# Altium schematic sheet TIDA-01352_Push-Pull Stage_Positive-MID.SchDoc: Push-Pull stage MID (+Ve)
size 431 x 279 mm; Date: Not shown in title block; ApprovedBy: Not shown in title block; CheckedBy: Not shown in title block; Author: Not shown in title block; CompanyName: Not shown in title block; DrawnBy: Sanjay Pithadia; Engineer: Sanjay Pithadia; Organization: Not shown in title block; Address1: Not shown in title block; Address2: Not shown in title block; Address3: Not shown in title block; Address4: Not shown in title block; DocumentNumber: 1; Revision: Use project parameter SCH_Rev; SheetNumber: 7; SheetTotal: 9; PageSetup: Record=PageOptions¦CenterHorizontal=True¦CenterVertical=True¦PrintScale=1.00¦XCorrection=1.00¦YCorrection=1.00¦PrintKind=0¦BorderSize=5000000¦LeftOffset=0¦BottomOffset=0¦Orientation=2¦PaperLength=1000¦PaperWidth=1000¦Scale=100¦PaperSource=15¦PrintQuality=600¦MediaType=1¦DitherType=10¦PaperKind=Letter¦PrintScaleMode=1
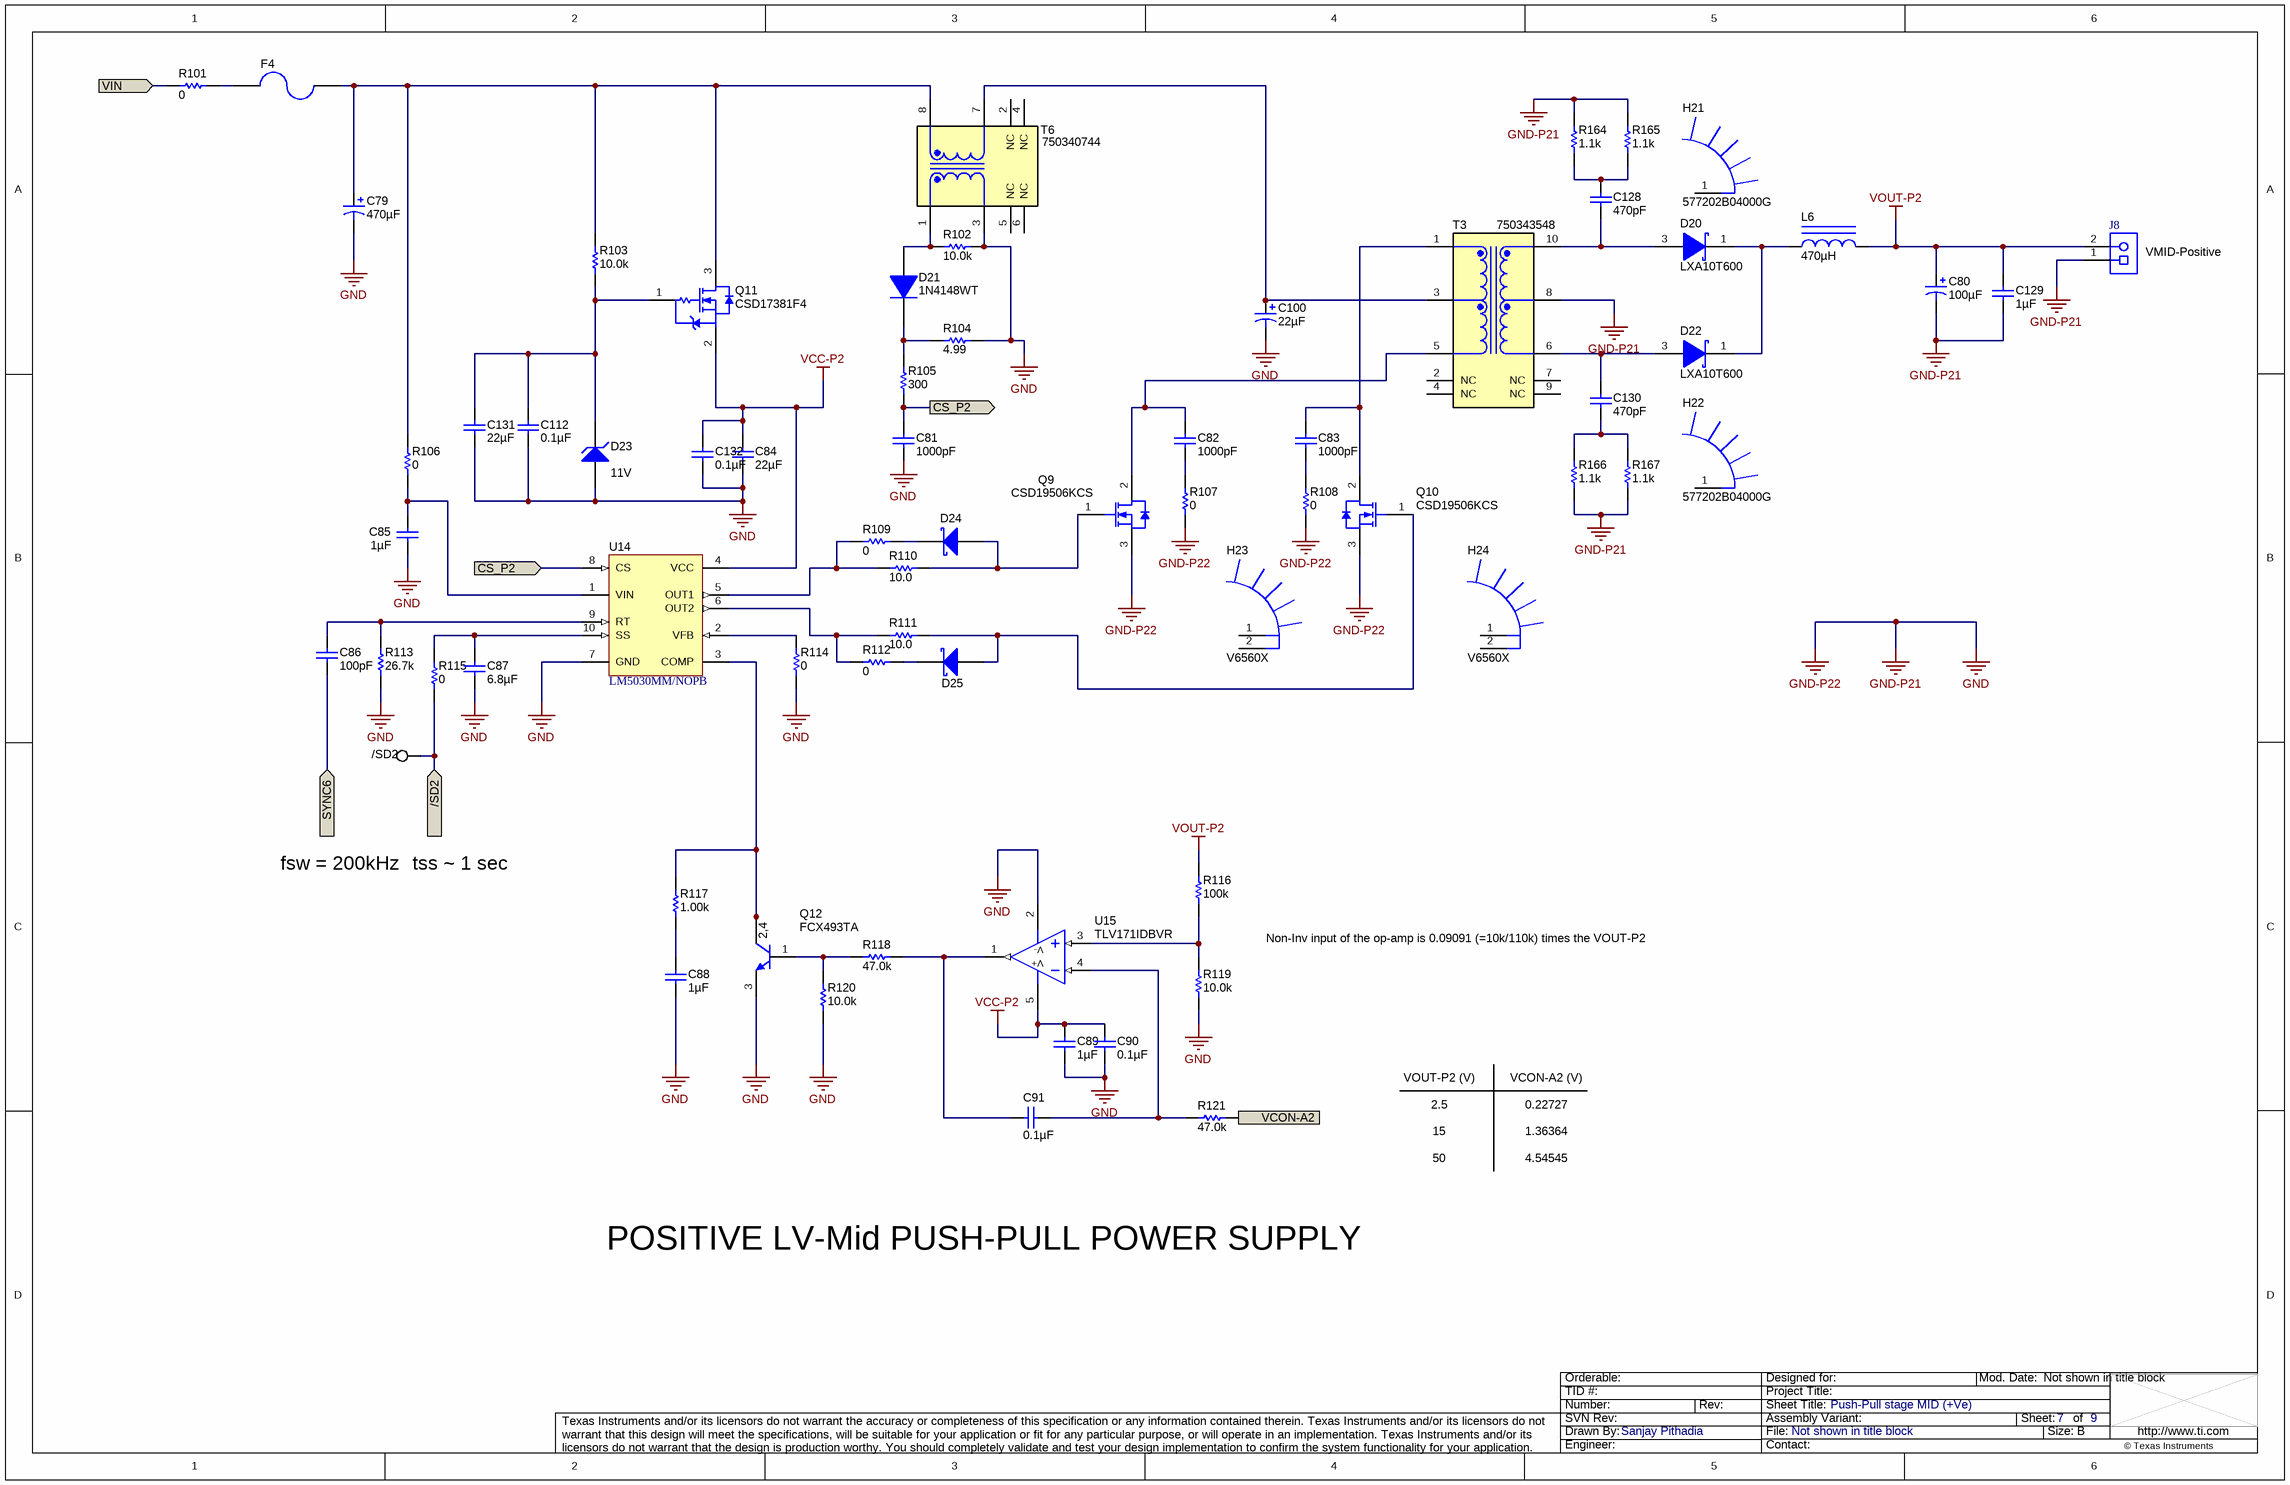
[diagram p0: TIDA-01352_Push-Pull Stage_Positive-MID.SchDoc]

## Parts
/SD2  5002  [Keystone5002]  (value not drawn)
C79  ValueDisplayed: 470µF  [WCAP-ATLI_1300x3000]  (hidden comment: 860080778023)
C80  ValueDisplayed: 100µF  [Nichicon_2000x3000_Snap]  (hidden comment: LLS2G101MELY)
C81  ValueDisplayed: 1000pF  [0603]  (hidden comment: GRM188R71E102KA01D)
C82  ValueDisplayed: 1000pF  [0603]  (hidden comment: GRM188R71E102KA01D)
C83  ValueDisplayed: 1000pF  [0603]  (hidden comment: GRM188R71E102KA01D)
C84  ValueDisplayed: 22µF  [1210_280]  (hidden comment: 12103D226MAT2A)
C85  ValueDisplayed: 1µF  [0805_HV]  (hidden comment: 08055C105KAT2A)
C86  ValueDisplayed: 100pF  [0603]  (hidden comment: 06035A101FAT2A)
C87  ValueDisplayed: 6.8µF  [0603]  (hidden comment: C1608X5R1E685K080AC)
C88  ValueDisplayed: 1µF  [0603]  (hidden comment: GMK107BJ105KA-T)
C89  ValueDisplayed: 1µF  [0805_HV]  (hidden comment: 08055C105KAT2A)
C90  ValueDisplayed: 0.1µF  [0603]  (hidden comment: 06035C104KAT2A)
C91  ValueDisplayed: 0.1µF  [0603]  (hidden comment: 06035C104KAT2A)
C100  ValueDisplayed: 22µF  [SM_RADIAL_E]  (hidden comment: EEE-FC1H220P)
C112  ValueDisplayed: 0.1µF  [0603]  (hidden comment: 06035C104KAT2A)
C128  ValueDisplayed: 470pF  [1206]  (hidden comment: VJ1206Y471KBEAT4X)
C129  ValueDisplayed: 1µF  [2220_200]  (hidden comment: GRM55DR72E105KW01L)
C130  ValueDisplayed: 470pF  [1206]  (hidden comment: VJ1206Y471KBEAT4X)
C131  ValueDisplayed: 22µF  [1210_280]  (hidden comment: 12103D226MAT2A)
C132  ValueDisplayed: 0.1µF  [0603]  (hidden comment: 06035C104KAT2A)
D20  LXA10T600  [TO-220AC]
D21  1N4148WT  [Fairchild_SOD-523F]
D22  LXA10T600  [TO-220AC]
D23  value 11V  [SMA]  (hidden comment: 1SMA5926BT3G)
D24  PMEG1030EJ,115  [SOD-323F]  (value not drawn)
D25  PMEG1030EJ,115  [SOD-323F]  (value not drawn)
F4  0679L9100-01  [Fuse_SSQ]  (value not drawn)
H21  577202B04000G  [Aavid_577202B04000G]
H22  577202B04000G  [Aavid_577202B04000G]
H23  V6560X  [ASMN_V6560X]
H24  V6560X  [ASMN_V6560X]
J8  1727010  [PhoenixConact_1727010]  (value not drawn)
L6  ValueDisplayed: 470µH  [1447440C]  (hidden comment: 1447440C)
Q9  CSD19506KCS  [KCS0003B]
Q10  CSD19506KCS  [KCS0003B]
Q11  CSD17381F4  [YJC0003A]
Q12  FCX493TA  [SOT-89-3]
R101  ValueDisplayed: 0  [5108]  (hidden comment: 5108)
R102  ValueDisplayed: 10.0k  [0603]  (hidden comment: CRCW060310K0FKEA)
R103  ValueDisplayed: 10.0k  [0603]  (hidden comment: CRCW060310K0FKEA)
R104  ValueDisplayed: 4.99  [0805_HV]  (hidden comment: CRCW08054R99FKEA)
R105  ValueDisplayed: 300  [0603]  (hidden comment: RC0603FR-07300RL)
R106  ValueDisplayed: 0  [0603]  (hidden comment: CRCW06030000Z0EA)
R107  ValueDisplayed: 0  [0603]  (hidden comment: CRCW06030000Z0EA)
R108  ValueDisplayed: 0  [0603]  (hidden comment: CRCW06030000Z0EA)
R109  ValueDisplayed: 0  [0603]  (hidden comment: CRCW06030000Z0EA)
R110  ValueDisplayed: 10.0  [0603]  (hidden comment: CRCW060310R0FKEA)
R111  ValueDisplayed: 10.0  [0603]  (hidden comment: CRCW060310R0FKEA)
R112  ValueDisplayed: 0  [0603]  (hidden comment: CRCW06030000Z0EA)
R113  ValueDisplayed: 26.7k  [0603]  (hidden comment: CRCW060326K7FKEA)
R114  ValueDisplayed: 0  [0603]  (hidden comment: CRCW06030000Z0EA)
R115  ValueDisplayed: 0  [0603]  (hidden comment: CRCW06030000Z0EA)
R116  ValueDisplayed: 100k  [1206]  (hidden comment: CRCW1206100KFKEA)
R117  ValueDisplayed: 1.00k  [0603]  (hidden comment: CRCW06031K00FKEA)
R118  ValueDisplayed: 47.0k  [0603]  (hidden comment: RC0603FR-0747KL)
R119  ValueDisplayed: 10.0k  [1206]  (hidden comment: CRCW120610K0FKEA)
R120  ValueDisplayed: 10.0k  [0603]  (hidden comment: CRCW060310K0FKEA)
R121  ValueDisplayed: 47.0k  [0603]  (hidden comment: RC0603FR-0747KL)
R164  ValueDisplayed: 1.1k  [PR01]  (hidden comment: PR01000101101JR500)
R165  ValueDisplayed: 1.1k  [PR01]  (hidden comment: PR01000101101JR500)
R166  ValueDisplayed: 1.1k  [PR01]  (hidden comment: PR01000101101JR500)
R167  ValueDisplayed: 1.1k  [PR01]  (hidden comment: PR01000101101JR500)
T3  750343548  [Wurth_750343473]
T6  750340744  [Wurth_750340744]
U14  LM5030MM/NOPB  [MUB10A_N]
U15  TLV171IDBVR  [DBV0005A_N]

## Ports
/SD2 (in), CS_P2 (in), CS_P2 (out), SYNC6 (in), VCON-A2 (in), VIN (in)

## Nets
GND: C79.2(-) C80.2(-) C81.2 C84.2 C85.2 C87.2 C88.2 C89.2 C90.2 C100.2(-) C112.2 C129.2 C131.2 C132.2 D23.2(A) J8.1 Q9.3(S) Q10.3(S) Q12.3(E) R102.1 R104.2 R107.2 R108.2 R113.1 R114.1 R119.1 R120.1 R164.2 R165.2 R166.1 R167.1 T3.8 T6.3 U14.7(GND) U15.2(V-)  [also labelled GND-P21, GND-P22]
VCC-P2: C84.1 C89.1 C90.1 C132.1 Q11.2(S) U14.4(VCC) U15.5(V+)
VOUT-P2: C80.1(+) C129.1 J8.2 L6.2 R116.2
/SD2: /SD2.1 R115.1 ; port /SD2
CS_P2: C81.1 R105.1 U14.8(CS) ; port CS_P2
SYNC6: C86.2 ; port SYNC6
VCON-A2: R121.2 ; port VCON-A2
VIN: R101.1 ; port VIN
NetC79_1: C79.1(+) F4.1 Q11.3(D) R103.2 R106.2 T6.8
NetC82_1: C82.1 Q9.2(D) T3.5
NetC82_2: C82.2 R107.1
NetC83_1: C83.1 Q10.2(D) T3.1
NetC83_2: C83.2 R108.1
NetC85_1: C85.1 R106.1 U14.1(VIN)
NetC86_1: C86.1 R113.2 U14.9(RT)
NetC87_1: C87.1 R115.2 U14.10(SS)
NetC88_1: C88.1 R117.1
NetC91_1: C91.1 R121.1 U15.4(IN-)
NetC91_2: C91.2 R118.2 U15.1(OUT)
NetC100_1: C100.1(+) T3.3 T6.7
NetC112_1: C112.1 C131.1 D23.1(K) Q11.1(G) R103.1
NetC128_1: C128.1 R164.1 R165.1
NetC128_2: C128.2 D20.3(K) T3.10
NetC130_1: C130.1 D22.3(K) T3.6
NetC130_2: C130.2 R166.2 R167.2
NetD20_1: D20.1(A) D22.1(A) L6.1
NetD21_1: D21.1(K) R104.1 R105.2
NetD21_2: D21.2(A) R102.2 T6.1
NetD24_1: D24.1(K) R109.1
NetD24_2: D24.2(A) Q9.1(G) R110.2
NetD25_1: D25.1(K) R112.1
NetD25_2: D25.2(A) Q10.1(G) R111.2
NetF4_2: F4.2 R101.2
NetQ12_1: Q12.1(B) R118.1 R120.2
NetQ12_2: Q12.2(C) Q12.4(C) R117.2 U14.3(COMP)
NetR109_2: R109.2 R110.1 U14.5(OUT1)
NetR111_1: R111.1 R112.2 U14.6(OUT2)
NetR114_2: R114.2 U14.2(VFB)
NetR116_1: R116.1 R119.2 U15.3(IN+)

Not connected (* = marked no-connect by the designer): H21 1; H22 1; H23 1 2; H24 1 2; T3 2(NC) 4(NC) 7(NC) 9(NC); T6 2(NC) 4(NC) 5(NC) 6(NC)

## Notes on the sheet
- (near J8) VMID-Positive
- fsw = 200kHz
- tss ~ 1 sec
- Non-Inv input of the op-amp is 0.09091 (=10k/110k) times the VOUT-P2
- VOUT-P2 (V)
- 2.5
- VCON-A2 (V)
- 0.22727
- 15
- 50
- 1.36364
- 4.54545
- POSITIVE LV-Mid PUSH-PULL POWER SUPPLY

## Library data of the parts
/SD2 = 5002: Test Point, Miniature, White, TH; Manufacturer: Keystone; CompType: Test Point Loop; ContactFinish: Silver
C79 = 860080778023: CAP, AL, 470 µF, 63 V, +/- 20%, TH; Manufacturer: Wurth Elektronik; Polarized: Y; CompType: Capacitor; Value: 470uF; U/M: EA; Cap_F: 0.00047; Tolerance_%: 20; Value1: Unknown; VDC_V: 63; Value2: 63V; IRMS_A: 2.225; TaMin_C: -55; TaMax_C: 105; Cap_Case: 13x30mm; SizeAreaWB_mm2: 225; SizeArea_mm2: 169; SizeX_mm: 13; SizeZ_mm: 31.5; AEC Category: Q200; AEC Qualified: N
C80 = LLS2G101MELY: CAP, AL, 100 µF, 400 V, +/- 20%, TH; Manufacturer: Nichicon; Polarized: Y; CompType: Capacitor; Value: 100uF; U/M: EA; Cap_F: 0.0001; Tolerance_%: 20; Value1: Unknown; VDC_V: 400; Value2: 400V; IRMS_A: 0.95; TaMin_C: -25; TaMax_C: 85; Cap_Case: 20x30mm; SizeAreaWB_mm2: 484; SizeZ_mm: 32; AEC Category: Q200; AEC Qualified: N
C81-C83 = GRM188R71E102KA01D: CAP, CERM, 1000 pF, 25 V, +/- 10%, X7R, 0603; Manufacturer: MuRata; Polarized: N; CompType: Capacitor; Value: 1000pF; U/M: EA; Cap_F: 0.000000001; Tolerance_%: 10; Value1: Unknown; VDC_V: 25; Value2: 25V; TaMin_C: -55; TaMax_C: 125; SizeArea_mm2: 1.28; SizeAreaWB_mm2: 4.68; SizeX_mm: 1.6; SizeY_mm: 0.8; SizeZ_mm: 1; AEC Category: Q200
C84 C131 = 12103D226MAT2A: CAP, CERM, 22 µF, 25 V, +/- 20%, X5R, 1210; Manufacturer: AVX; Polarized: N; CompType: Capacitor; Value: 22uF; U/M: EA; Cap_F: 0.000022; Tolerance_%: 20; Value1: Unknown; VDC_V: 25; Value2: 25V; TaMin_C: -55; TaMax_C: 85; Cap_Case: 1210; SizeArea_mm2: 8; SizeAreaWB_mm2: 14.7; SizeX_mm: 3.2; SizeY_mm: 2.5; SizeZ_mm: 2.8; AEC Category: Q200
C85 C89 = 08055C105KAT2A: CAP, CERM, 1 µF, 50 V, +/- 10%, X7R, 0805; Manufacturer: AVX; Polarized: N; CompType: Capacitor; Value: 1uF; U/M: EA; Cap_F: 0.000001; Tolerance_%: 10; Value1: Unknown; VDC_V: 50; Value2: 50V; TaMin_C: -55; TaMax_C: 125; Cap_Case: 0805; SizeArea_mm2: 2.5; SizeAreaWB_mm2: 6.75; SizeX_mm: 2; SizeY_mm: 1.25; SizeZ_mm: 1.45; AEC Category: Q200
C86 = 06035A101FAT2A: CAP, CERM, 100 pF, 50 V, +/- 1%, C0G/NP0, 0603; Manufacturer: AVX; Polarized: N; CompType: Capacitor; Value: 100pF; U/M: EA; Cap_F: 0.0000000001; Tolerance_%: 1; Value1: Unknown; VDC_V: 50; Value2: 50V; TaMin_C: -55; TaMax_C: 125; SizeArea_mm2: 1.28; SizeAreaWB_mm2: 4.68; SizeX_mm: 1.6; SizeY_mm: 0.8; AEC Category: Q200
C87 = C1608X5R1E685K080AC: CAP, CERM, 6.8 µF, 25 V, +/- 10%, X5R, 0603; Manufacturer: TDK; Polarized: N; CompType: Capacitor; Value: 6.8uF; U/M: EA; Cap_F: 0.0000068; Tolerance_%: 10; ESR_ohm: 0.004211; Value1: 0.004211 ohm; VDC_V: 25; Value2: 25V; IRMS_A: 2.534067; TaMin_C: -55; TaMax_C: 85; SizeArea_mm2: 1.28; SizeAreaWB_mm2: 4.68; SizeX_mm: 1.6; SizeY_mm: 0.8; SizeZ_mm: 1; AEC Category: Q200
C88 = GMK107BJ105KA-T: CAP, CERM, 1 µF, 35 V, +/- 10%, X5R, 0603; Manufacturer: Taiyo Yuden; Polarized: N; CompType: Capacitor; Value: 1uF; U/M: EA; Cap_F: 0.000001; Tolerance_%: 10; Value1: Unknown; VDC_V: 35; Value2: 35V; TaMin_C: -55; TaMax_C: 85; SizeArea_mm2: 1.28; SizeAreaWB_mm2: 4.68; SizeX_mm: 1.6; SizeY_mm: 0.8; SizeZ_mm: 1; AEC Category: Q200
C90 C91 C112 C132 = 06035C104KAT2A: CAP, CERM, 0.1 µF, 50 V, +/- 10%, X7R, 0603; Manufacturer: AVX; Polarized: N; CompType: Capacitor; Value: 0.1uF; U/M: EA; Cap_F: 0.0000001; Tolerance_%: 10; Value1: Unknown; VDC_V: 50; Value2: 50V; TaMin_C: -55; TaMax_C: 125; SizeArea_mm2: 1.28; SizeAreaWB_mm2: 4.68; SizeX_mm: 1.6; SizeY_mm: 0.8; SizeZ_mm: 1; AEC Category: Q200
C100 = EEE-FC1H220P: CAP, AL, 22 µF, 50 V, +/- 20%, 0.7 ohm, SMD; Manufacturer: Panasonic; Polarized: Y; CompType: Capacitor; Value: 22uF; U/M: EA; Cap_F: 0.000022; Tolerance_%: 20; Value1: 0.7 ohm; VDC_V: 50; Value2: 50V; ESR_ohm: 0.7; IRMS_A: 0.12; TaMin_C: -40; TaMax_C: 105; Cap_Case: E; SizeAreaWB_mm2: 118.45; SizeArea_mm2: 78.85; SizeX_mm: 9.5; SizeY_mm: 8.3; SizeZ_mm: 6.2; AEC Category: Q200
C128 C130 = VJ1206Y471KBEAT4X: CAP, CERM, 470 pF, 500 V, +/- 10%, X7R, 1206; Manufacturer: Vishay-Vitramon; Polarized: N; CompType: Capacitor; Value: 470pF; U/M: EA; Cap_F: 0.00000000047; Tolerance_%: 10; Value1: Unknown; VDC_V: 500; Value2: 500V; TaMin_C: -55; TaMax_C: 125; SizeArea_mm2: 5.12; SizeAreaWB_mm2: 10.92; SizeX_mm: 3.2; SizeY_mm: 1.6; SizeZ_mm: 1.35; AEC Category: Q200
C129 = GRM55DR72E105KW01L: CAP, CERM, 1 µF, 250 V, +/- 10%, X7R, 2220; Manufacturer: MuRata; Polarized: N; CompType: Capacitor; Value: 1uF; U/M: EA; Cap_F: 0.000001; Tolerance_%: 10; ESR_ohm: 0.007086; Value1: 0.007086 ohm; VDC_V: 250; Value2: 250V; IRMS_A: 2.0605; TaMin_C: -55; TaMax_C: 125; Cap_Case: 2220; SizeArea_mm2: 28.5; SizeAreaWB_mm2: 53.9; SizeX_mm: 5.7; SizeY_mm: 5; SizeZ_mm: 2; AEC Category: Q200
D20 D22 = LXA10T600: Diode, Schottky, 600 V, 10 A, TH; Manufacturer: Power Integrations; SymbolCreator: a0412235; U/M: EA; Vf_V: 2.4; Value: 600V; Value1: 10A; Value2: 2.4V; Io_A: 10; Vr_V: 600; TJmax_C: 150; RJC_CperW: 1.4; SizeAreaWB_mm2: 78.975; SizeArea_mm2: 45.675; SizeX_mm: 10.15; SizeY_mm: 4.5; SizeZ_mm: 23; AEC Category: Q101; AEC Qualified: N
D21 = 1N4148WT: Diode, Switching, 75 V, 0.3 A, SOD-523F; Manufacturer: Fairchild Semiconductor; U/M: EA; Value: 75V; Value1: 0.3A; Io_A: 0.3; Vr_V: 75; TJmax_C: 150; SizeAreaWB_mm2: 4.68; SizeArea_mm2: 1.28; SizeX_mm: 1.6; SizeY_mm: 0.8; SizeZ_mm: 0.7; AEC Category: Q101
D23 = 1SMA5926BT3G: Diode, Zener, 11 V, 1.5 W, SMA; Manufacturer: ON Semiconductor; SymbolCreator: a0412235; U/M: EA; Power_W: 1.5; Vz_V: 11; Value1: 1.5W; RJA_CperW: 250; SizeAreaWB_mm2: 37.3428; SizeArea_mm2: 16.3228; SizeX_mm: 5.59; SizeY_mm: 2.92; SizeZ_mm: 2.87; AEC Category: Q101
D24 D25 = PMEG1030EJ,115: Diode, Schottky, 10 V, 3 A, SOD-323F; Manufacturer: NXP Semiconductor; U/M: EA; Vf_V: 0.53; Value: 10V; Value1: 3A; Value2: 0.53V; Io_A: 3; Vr_V: 10; TJmax_C: 150; SizeAreaWB_mm2: 7.875; SizeArea_mm2: 3.125; SizeX_mm: 2.5; SizeY_mm: 1.25; SizeZ_mm: 0.8; AEC Category: Q101; AEC Qualified: N
F4 = SSQ 8: FUSE BRD MNT 10A 125VAC/VDC; Manufacturer: Bel Fuse; VDC_V: 125; Interrupt_AC: 50; Irating_A: 8; Rtyp_Ohm: 0.008; MeltingTyp: 26
H21 H22 = 577202B04000G: HEATSINK TO-220 .500" COMPACT; Manufacturer: Aavid; SymbolCreator: a0412235
H23 H24 = V6560X: HEATSINK, ALUM, ANOD, for TO-220; Manufacturer: Assman WSW; SymbolCreator: a0799628
J8 = 1727010: Conn Term Block, 2POS, 3.81mm, TH; Manufacturer: Phoenix Contact; SymbolCreator: a0412235; CompType: Terminal Block
L6 = 1447440C: Inductor, Wirewound, 470 µH, 4 A, 0.125 ohm, TH; Manufacturer: MuRata; Value: 470uH; Ind_H: 470.0E-6; Imax_A: 4; Irms: 4A @ 50C rise; Isat: 4A @ 40% inductance drop; DCR_ohm: 0.125; Value2: 4A; SizeAreaWB_mm2: 1071.66; SizeArea_mm2: 944.66; SizeX_mm: 31.7; SizeY_mm: 29.8; SizeZ_mm: 23.5; AEC Category: Q200; AEC Qualified: N
Q9 Q10 = CSD19506KCS: MOSFET, N-CH, 80 V, 100 A, KCS0003B (TO-220-3); Manufacturer: Texas Instruments; Alternate Manufacturer: None; U/M: EA; ChType: N; Value: 80V; VdsMax_V: 80; Value1: ? ohm; Value2: 120 nC; QgTyp_nC: 120; Vgs_V: 20; IdsMax_A: 100; SizeAreaWB_mm2: 79.648; SizeArea_mm2: 46.228; SizeX_mm: 4.55; SizeY_mm: 10.16; SizeZ_mm: 20.45; AEC Category: Q101
Q11 = CSD17381F4: MOSFET, N-CH, 30 V, 3.1 A, YJC0003A (PICOSTAR-3); Manufacturer: Texas Instruments; Alternate Manufacturer: None; SymbolCreator: a0411947; U/M: EA; ChType: N; Value: 30V; VdsMax_V: 30; Value1: 0.09 ohm; Rdson45_ohm: 0.09; Value2: 1.04 nC; QgTyp_nC: 1.04; Vgs_V: 12; IdsMax_A: 3.1; SizeAreaWB_mm2: 3.327225; SizeArea_mm2: 0.657225; SizeX_mm: 1.035; SizeY_mm: 0.635; SizeZ_mm: 0.35; AEC Category: Q101
Q12 = FCX493TA, Diodes Inc.: Transistor, NPN, 100 V, 1 A, SOT-89; SymbolCreator: a0412235; PNP: 0; NPN: 1; Vceo_V: 100; Vcesat1_V: 0.6; Value: 100 V; Value1: 1 A; HfeMax: 300; TaMin_C: -65; TaMax_C: 150; CompType: BJT; U/M: EA; AEC Category: Q101; SizeAreaWB_mm2: 28.05; SizeArea_mm2: 18.45; SizeX_mm: 4.1; SizeY_mm: 4.5; SizeZ_mm: 1.5
R101 = 5108: RES, 0, 1%, 0.5 W, 1206; Manufacturer: Keystone; CompType: Resistor; Value: 0; Tolerance_%: 1; Power_W: 0.5; Value2: 0.5W; TempCo: ppm/C; SizeArea_mm2: 5.185; SizeX_mm: 3.05; SizeY_mm: 1.7; SizeZ_mm: 0.84; U/M: EA; AEC Category: Q200; AEC Qualified: N
R102 R103 R120 = CRCW060310K0FKEA: RES, 10.0 k, 1%, 0.1 W, 0603; Manufacturer: Vishay-Dale; CompType: Resistor; Value: 10.0k; Res_ohm: 10000; Value_Code: 10k0; Tolerance_%: 1; Power_W: 0.1; Value2: 0.1W; VDC_V: 75; TempCo: 100 ppm/C; SizeArea_mm2: 1.28; SizeX_mm: 1.6; SizeY_mm: 0.8; EIA_Code: E96; U/M: EA; AEC Category: Q200
R104 = CRCW08054R99FKEA: RES, 4.99, 1%, 0.125 W, 0805; Manufacturer: Vishay-Dale; CompType: Resistor; Value: 4.99; Value_Code: 4R99; Tolerance_%: 1; Power_W: 0.125; Value2: 0.125W; VDC_V: 150; TempCo: 100 ppm/C; SizeArea_mm2: 2.5; SizeX_mm: 2; SizeY_mm: 1.25; SizeZ_mm: 1.45; EIA_Code: E96; U/M: EA; AEC Category: Q200
R105 = RC0603FR-07300RL: RES, 300, 1%, 0.1 W, 0603; Manufacturer: Yageo America; CompType: Resistor; Value: 300; Value_Code: 300R; Tolerance_%: 1; Power_W: 0.1; Value2: 0.1W; VDC_V: 150; TempCo: 200 ppm/C; SizeArea_mm2: 1.28; SizeX_mm: 1.6; SizeY_mm: 0.8; U/M: EA; AEC Category: Q200
R106-R109 R112 R114 R115 = CRCW06030000Z0EA: RES, 0, 5%, 0.1 W, 0603; Manufacturer: Vishay-Dale; CompType: Resistor; Value: 0; Value_Code: 0000; Tolerance_%: 5; Power_W: 0.1; Value2: 0.1W; VDC_V: 75; TempCo: 200 ppm/C; SizeArea_mm2: 1.28; SizeX_mm: 1.6; SizeY_mm: 0.8; SizeZ_mm: 1; EIA_Code: E24; U/M: EA; AEC Category: Q200
R110 R111 = CRCW060310R0FKEA: RES, 10.0, 1%, 0.1 W, 0603; Manufacturer: Vishay-Dale; CompType: Resistor; Value: 10.0; Res_ohm: 10; Value_Code: 10R0; Tolerance_%: 1; Power_W: 0.1; Value2: 0.1W; VDC_V: 75; TempCo: 100 ppm/C; SizeArea_mm2: 1.28; SizeX_mm: 1.6; SizeY_mm: 0.8; EIA_Code: E96; U/M: EA; AEC Category: Q200
R113 = CRCW060326K7FKEA: RES, 26.7 k, 1%, 0.1 W, 0603; Manufacturer: Vishay-Dale; CompType: Resistor; Value: 26.7k; Res_ohm: 26700; Value_Code: 26k7; Tolerance_%: 1; Power_W: 0.1; Value2: 0.1W; VDC_V: 75; TempCo: 100 ppm/C; SizeArea_mm2: 1.28; SizeX_mm: 1.6; SizeY_mm: 0.8; EIA_Code: E96; U/M: EA; AEC Category: Q200
R116 = CRCW1206100KFKEA: RES, 100 k, 1%, 0.25 W, 1206; Manufacturer: Vishay-Dale; CompType: Resistor; Value: 100k; Res_ohm: 100000; Tolerance_%: 1; Power_W: 0.25; Value2: 0.25W; VDC_V: 200; TempCo: 100 ppm/C; SizeArea_mm2: 5.12; SizeX_mm: 3.2; SizeY_mm: 1.6; SizeZ_mm: 1.35; EIA_Code: E96; U/M: EA; AEC Category: Q200; Green_Lifecycle: Active; Green_REACh: Passed
R117 = CRCW06031K00FKEA: RES, 1.00 k, 1%, 0.1 W, 0603; Manufacturer: Vishay-Dale; CompType: Resistor; Value: 1.00k; Res_ohm: 1000; Value_Code: 1k00; Tolerance_%: 1; Power_W: 0.1; Value2: 0.1W; VDC_V: 75; TempCo: 100 ppm/C; SizeArea_mm2: 1.28; SizeX_mm: 1.6; SizeY_mm: 0.8; EIA_Code: E96; U/M: EA; AEC Category: Q200
R118 R121 = RC0603FR-0747KL: RES, 47.0 k, 1%, 0.1 W, 0603; Manufacturer: Yageo America; CompType: Resistor; Value: 47.0k; Res_ohm: 47000; Value_Code: 47k0; Tolerance_%: 1; Power_W: 0.1; Value2: 0.1W; VDC_V: 150; TempCo: 200 ppm/C; SizeArea_mm2: 1.28; SizeX_mm: 1.6; SizeY_mm: 0.8; U/M: EA; AEC Category: Q200
R119 = CRCW120610K0FKEA: RES, 10.0 k, 1%, 0.25 W, 1206; Manufacturer: Vishay-Dale; CompType: Resistor; Value: 10.0k; Res_ohm: 10000; Value_Code: 10k0; Tolerance_%: 1; Power_W: 0.25; Value2: 0.25W; VDC_V: 200; TempCo: 100 ppm/C; SizeArea_mm2: 5.12; SizeX_mm: 3.2; SizeY_mm: 1.6; SizeZ_mm: 1.35; EIA_Code: E96; U/M: EA; AEC Category: Q200
R164-R167 = PR01000101101JR500: RES, 1.1 k, 5%, 1 W, AEC-Q200 Grade 0, D2.5xL6.5mm; Manufacturer: Vishay-Bccomponents; CompType: Resistor; Value: 1.1k; Res_ohm: 1100; Value_Code: 1k10; Tolerance_%: 5; Power_W: 1; Value2: 1W; VDC_V: 350; TempCo: 250 ppm/C; EIA_Code: E24; U/M: EA; AEC Category: Q200; AEC Qualified: Y; AEC Grade: 0
T3 = 750343548: Transformer, 100 uH, TH; Manufacturer: Wurth Elektronik; SymbolCreator: Altium; ValueDisplayed: 100µH; Value: 100uH; DCR_ohm: 0.025; Lp: 100; Ind_H: 0.0001; Ns1toNp: 3; Rsec1_ohm: 0.058; Rsec2_ohm: 0.08; SizeAreaWB_mm2: 934.4274; SizeArea_mm2: 816.1274; SizeX_mm: 29.21; SizeY_mm: 27.94; SizeZ_mm: 21.59
T6 = 750340744: Transformer, TH; Manufacturer: Wurth Elektronik; SymbolCreator: Altium; ValueDisplayed: 2mH; Value: 2mH; Lp: 2000; Ns1toNp: 100; Rs1: 5.87; SizeAreaWB_mm2: 94.9181; SizeArea_mm2: 59.9181; SizeX_mm: 8.13; SizeY_mm: 7.37; SizeZ_mm: 5.46
U14 = LM5030MM/NOPB: 100V Push-Pull Current Mode PWM Controller, 10-pin MSOP, Pb-Free; Manufacturer: Texas Instruments; PackageTopMarking: ZXTT*S73B; PowerWise: Y; CompType: Switcher
U15 = TLV171IDBVR: 36-V, Single-Supply, Low-Power Operational Amplifiers for Cost-Sensitive Systems, DBV0005A (SOT-5); Alternate PartNumber: TLV171IDBVT; Manufacturer: Texas Instruments; SizeArea_mm2: 8.12; SizeAreaWB_mm2: 14.82; SizeX_mm: 2.8; SizeY_mm: 2.9; SizeZ_mm: 1.45; CompType: IC; U/M: EA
